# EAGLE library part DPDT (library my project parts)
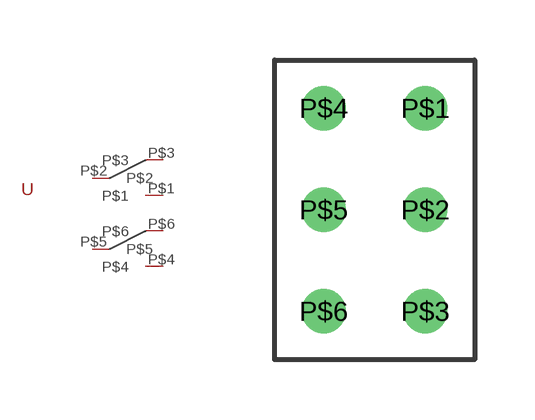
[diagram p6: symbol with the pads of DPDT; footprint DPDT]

Designator prefix -

## DPDT  [DPDT]
P$1  P$1
P$2  P$2
P$3  P$3
P$4  P$4
P$5  P$5
P$6  P$6

## Footprint DPDT (pad centres in mm)
drill 0.6 round: P$1 1.27,2.54; P$2 1.27,0; P$3 1.27,-2.54; P$4 -1.27,2.54; P$5 -1.27,0; P$6 -1.27,-2.54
